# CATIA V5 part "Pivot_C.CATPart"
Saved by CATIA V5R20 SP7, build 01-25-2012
Part number: Pivot_C
Bounding box of the stored display mesh (mm): x -2.5 to 2.5, y 107.5 to 112.5, z -55 to -43
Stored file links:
  D:\IFMA\COURS\2A\projet balance IAO\catia\Pivot_C.CATPart
  D:\IFMA\COURS\2A\projet balance IAO\catia\Ass_projet_balance.CATProduct
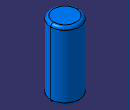
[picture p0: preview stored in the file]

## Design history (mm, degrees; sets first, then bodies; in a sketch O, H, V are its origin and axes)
Set1
  Plane1 "Plan_BC": linked copy from another document
  Point1 "Point.C": linked copy from another document
Body1 (main body)
  Sketch1 on Plane1, origin (0, 0, -49), H (1, 0, 0), V (0, 1, 0)
    circle A1 centre (0, 110) radius 2.5
    point P1 (0, 110)
    reference projected point E1 (0, 110) from Point1
    radius A1 = 2.5
    coincidence: P1 E1
  Pad1: profile Sketch1, direction (0, 0, 1), length 6, mirrored extent
  Fillet1: radius 0.5, on end face of Pad1; edge [start face of Pad1 | face of Pad1 from Sketch1.A1]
